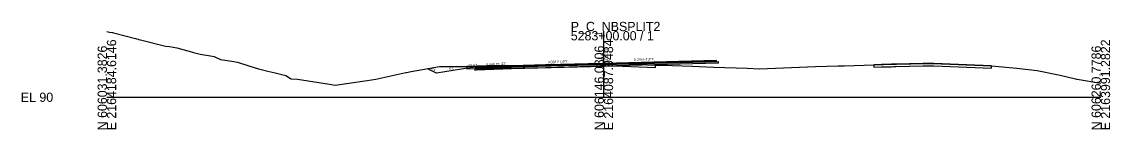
# Model space of a CAD drawing. Extents: x -26 to 1303, y -10 to 12038.
# Drawn here: x -25.7 to 302.8, y 1990.3 to 2022.8 of the extents above; entities that cross this region are included whole.
import ezdxf

# ---------------------------------------------------------------- set-up
doc = ezdxf.new("R2010")
doc.units = 0
for name, color, linetype in [('RD_GPK_XS_Cell', 7, 'Continuous'), ('RD_XS_Base', 7, 'Continuous'), ('RD_XS_ExGround', 7, 'Continuous'), ('RD_XS_ExPaveRet', 7, 'Continuous'), ('RD_XS_Greenside', 7, 'Continuous'), ('RD_XS_Pave', 7, 'Continuous'), ('RD_XS_PaveOvlay_CP', 7, 'Continuous'), ('RD_XS_TieSlope', 7, 'Continuous'), ('RD_XS_TX_Elev_EX', 7, 'Continuous'), ('RD_XS_TX_Elev_PR', 7, 'Continuous'), ('RD_XS_TX_ShdSlope', 7, 'Continuous'), ('RD_XS_TX_Slope', 7, 'Continuous')]:
    doc.layers.add(name, color=color, linetype=linetype)

msp = doc.modelspace()

# ---------------------------------------------------------------- linework, layer by layer
at = {"layer": 'RD_GPK_XS_Cell'}
for p, q in [((150, 2000), (150, 2020)), ((0, 2000), (150, 2000)), ((150, 2000), (300, 2000))]:
    msp.add_line(p, q, dxfattribs=at)
at = {"layer": 'RD_XS_Base'}
for p, q in [((150, 2009.89), (184.5, 2010.79)), ((184, 2010.78), (184, 2010.78)), ((184.5, 2010.79), (184.5, 2010.29)), ((184.5, 2010.76), (184.5, 2010.76)), ((111.52, 2008.75), (111.02, 2008.73)), ((111.02, 2008.73), (111.02, 2008.73)), ((111.02, 2008.73), (111.02, 2008.23)), ((111.02, 2008.23), (111.52, 2008.25)), ((122.09, 2009.17), (111.52, 2008.75)), ((111.52, 2008.75), (111.52, 2008.75)), ((111.52, 2008.25), (122.09, 2008.67)), ((111.52, 2008.25), (111.52, 2008.25)), ((150, 2009.89), (122.09, 2009.17)), ((122.09, 2008.67), (150, 2009.39)), ((138, 2009.58), (138, 2009.58)), ((138, 2009.08), (138, 2009.08)), ((184.5, 2010.29), (150, 2009.39)), ((150, 2009.39), (150, 2010.05)), ((150, 2010.05), (150, 2010.05)), ((150, 2010.05), (150, 2010.05)), ((150, 2010.05), (150, 2009.89)), ((150, 2009.89), (150, 2009.89)), ((150, 2009.39), (150, 2009.89)), ((150, 2009.89), (150, 2009.89)), ((150, 2009.89), (150, 2009.89)), ((150, 2009.39), (150, 2009.39)), ((174, 2010.52), (174, 2010.52)), ((174, 2010.52), (174, 2010.52)), ((174, 2010.02), (174, 2010.02)), ((174, 2010.02), (174, 2010.02))]:
    msp.add_line(p, q, dxfattribs=at)
at = {"layer": 'RD_XS_ExGround'}
msp.add_lwpolyline([(0, 2019.9), (0.83, 2019.72), (1.73, 2019.56), (1.99, 2019.5), (8.66, 2017.75), (8.98, 2017.66), (9.4, 2017.53), (9.57, 2017.49), (10.13, 2017.34), (17.69, 2015.48), (18.94, 2015.39), (21.1, 2014.91), (24.43, 2014.03), (24.85, 2013.9), (26.13, 2013.5), (28.13, 2012.98), (31.26, 2012.51), (32.39, 2012.28), (34.25, 2011.43), (37.72, 2010.87), (39.47, 2010.57), (42.85, 2009.53), (45.73, 2008.61), (46.21, 2008.5), (46.57, 2008.37), (48.58, 2007.91), (50.42, 2007.47), (53.98, 2006.6), (55.46, 2005.63), (55.55, 2005.57), (55.64, 2005.53), (57.55, 2005.43), (67.14, 2003.94), (68.92, 2003.69), (78.57, 2005.1), (81.17, 2005.5), (88.45, 2007.1), (90.26, 2007.49), (90.4, 2007.52), (91.79, 2007.76), (100.43, 2009.27), (101.15, 2009.27), (108.69, 2009.33), (114.75, 2009.45), (118.36, 2009.5), (118.48, 2009.5), (125.69, 2009.64), (132.36, 2009.77), (132.51, 2009.77), (132.73, 2009.78), (149.48, 2010.23), (149.75, 2010.26), (149.85, 2010.25), (150.35, 2010.27), (151.84, 2010.25), (155.64, 2010.12), (165.62, 2009.75), (170.67, 2009.59), (176.66, 2009.38), (183.16, 2009.12), (193.25, 2008.8), (196.96, 2008.63), (201.77, 2008.77), (213.84, 2009.32), (220.68, 2009.46), (222.67, 2009.52), (225.68, 2009.62), (231.5, 2009.83), (234.44, 2009.91), (237.59, 2009.98), (238.36, 2010.02), (247.11, 2010.23), (247.32, 2010.22), (248.79, 2010.24), (249.41, 2010.22), (266.96, 2009.53), (274.69, 2008.82), (280.81, 2008.07), (286.7, 2006.87), (287.77, 2006.66), (292.35, 2005.57), (292.62, 2005.5), (292.62, 2005.5), (292.87, 2005.46), (300, 2004.27)], dxfattribs=at)
at = {"layer": 'RD_XS_ExPaveRet'}
for points in [[(165.62, 2009.75), (155.64, 2010.12), (155.64, 2010.12), (151.84, 2010.25), (150.35, 2010.27), (150.35, 2010.27), (150.35, 2010.27), (149.85, 2010.25), (149.75, 2010.26), (149.48, 2010.23), (149.48, 2010.23), (149.48, 2010.23), (149.48, 2010.23), (132.73, 2009.78), (132.73, 2009.78), (132.51, 2009.77), (132.36, 2009.77), (132.36, 2009.77), (125.69, 2009.64), (125.69, 2009.64), (118.48, 2009.5), (118.48, 2009.5), (118.36, 2009.5), (114.75, 2009.45), (114.75, 2009.45), (114.75, 2009.45), (108.69, 2009.33), (108.69, 2009.33), (108.69, 2009.33), (108.69, 2009.33), (108.69, 2008.58), (108.69, 2008.58), (108.69, 2008.58), (114.75, 2008.7), (114.75, 2008.7), (114.75, 2008.7), (118.36, 2008.75), (118.48, 2008.75), (118.48, 2008.75), (125.69, 2008.89), (125.69, 2008.89), (132.36, 2009.02), (132.36, 2009.02), (132.51, 2009.02), (132.73, 2009.03), (132.73, 2009.03), (149.48, 2009.48), (149.48, 2009.48), (149.48, 2009.48), (149.48, 2009.48), (149.75, 2009.51), (149.85, 2009.5), (150.35, 2009.52), (150.35, 2009.52), (150.35, 2009.52), (151.84, 2009.5), (155.64, 2009.37), (155.64, 2009.37), (165.62, 2009), (165.62, 2009), (165.62, 2009.75), (165.62, 2009.75), (165.62, 2009.75)], [(165.62, 2009.75), (155.64, 2010.12), (151.84, 2010.25), (150.35, 2010.27), (149.85, 2010.25), (149.75, 2010.26), (149.48, 2010.23), (132.73, 2009.78), (132.51, 2009.77), (132.36, 2009.77), (125.69, 2009.64), (118.48, 2009.5), (118.36, 2009.5), (114.75, 2009.45), (108.69, 2009.33), (108.69, 2008.58), (114.75, 2008.7), (118.36, 2008.75), (118.48, 2008.75), (125.69, 2008.89), (132.36, 2009.02), (132.51, 2009.02), (132.73, 2009.03), (149.48, 2009.48), (149.75, 2009.51), (149.85, 2009.5), (150.35, 2009.52), (151.84, 2009.5), (155.64, 2009.37), (165.62, 2009), (165.62, 2009.75)], [(266.96, 2009.53), (264.47, 2009.63), (249.6, 2010.22), (248.9, 2010.24), (248.81, 2010.24), (248.73, 2010.24), (247.44, 2010.22), (247.32, 2010.22), (247.17, 2010.23), (247.11, 2010.23), (246.61, 2010.22), (246.42, 2010.21), (238.17, 2010.01), (237.43, 2010), (236.85, 2009.96), (234.44, 2009.91), (233.77, 2009.9), (231.5, 2009.83), (231.5, 2009.74), (231.5, 2009.08), (233.77, 2009.15), (234.44, 2009.16), (236.85, 2009.21), (237.43, 2009.25), (238.17, 2009.26), (246.42, 2009.46), (246.61, 2009.47), (247.11, 2009.48), (247.17, 2009.48), (247.32, 2009.47), (247.44, 2009.47), (248.73, 2009.49), (248.81, 2009.49), (248.9, 2009.49), (249.6, 2009.47), (264.47, 2008.88), (266.96, 2008.78), (266.96, 2008.78), (266.96, 2008.78), (266.96, 2009.39), (266.96, 2009.53), (266.96, 2009.53), (266.96, 2009.53)], [(266.96, 2009.53), (264.47, 2009.63), (249.6, 2010.22), (248.9, 2010.24), (248.81, 2010.24), (248.73, 2010.24), (247.44, 2010.22), (247.32, 2010.22), (247.17, 2010.23), (247.11, 2010.23), (246.61, 2010.22), (246.42, 2010.21), (238.17, 2010.01), (237.43, 2010), (236.85, 2009.96), (234.44, 2009.91), (233.77, 2009.9), (231.5, 2009.83), (231.5, 2009.74), (231.5, 2009.08), (233.77, 2009.15), (234.44, 2009.16), (236.85, 2009.21), (237.43, 2009.25), (238.17, 2009.26), (246.42, 2009.46), (246.61, 2009.47), (247.11, 2009.48), (247.17, 2009.48), (247.32, 2009.47), (247.44, 2009.47), (248.73, 2009.49), (248.81, 2009.49), (248.9, 2009.49), (249.6, 2009.47), (264.47, 2008.88), (266.96, 2008.78), (266.96, 2008.78), (266.96, 2009.39), (266.96, 2009.53), (266.96, 2009.53)]]:
    msp.add_lwpolyline(points, dxfattribs=at)
at = {"layer": 'RD_XS_Greenside'}
for p, q in [((99.52, 2007.24), (96.74, 2008.62)), ((109.52, 2008.9), (99.52, 2007.24))]:
    msp.add_line(p, q, dxfattribs=at)
at = {"layer": 'RD_XS_Pave'}
for p, q in [((184, 2011.1), (150, 2010.21)), ((184, 2010.94), (150, 2010.05)), ((150, 2010.05), (184, 2010.94)), ((150, 2009.89), (184, 2010.78)), ((174, 2010.84), (174, 2010.84)), ((174, 2010.84), (174, 2010.84)), ((174, 2010.68), (174, 2010.68)), ((174, 2010.68), (174, 2010.68)), ((174, 2010.68), (174, 2010.68)), ((174, 2010.68), (174, 2010.68)), ((184, 2010.94), (184, 2011.1)), ((184, 2011.1), (184, 2011.1)), ((184, 2010.78), (184, 2010.94)), ((184, 2010.94), (184, 2010.94)), ((122.09, 2009.49), (111.52, 2009.06)), ((111.52, 2008.91), (122.09, 2009.33)), ((122.09, 2009.33), (111.52, 2008.91)), ((111.52, 2008.75), (122.09, 2009.17)), ((111.52, 2009.06), (111.52, 2009.06)), ((111.52, 2009.06), (111.52, 2008.91)), ((111.52, 2008.91), (111.52, 2008.91)), ((111.52, 2008.91), (111.52, 2008.75)), ((150, 2010.21), (122.09, 2009.49)), ((122.09, 2009.33), (150, 2010.05)), ((150, 2010.05), (122.09, 2009.33)), ((122.09, 2009.17), (150, 2009.89)), ((138, 2009.9), (138, 2009.9)), ((138, 2009.74), (138, 2009.74)), ((138, 2009.74), (138, 2009.74)), ((138, 2009.58), (138, 2009.58)), ((150, 2010.21), (150, 2010.21)), ((150, 2010.05), (150, 2010.05)), ((150, 2010.05), (150, 2010.05)), ((150, 2010.05), (150, 2009.89)), ((150, 2010.05), (150, 2010.05)), ((150, 2009.89), (150, 2010.05)), ((150, 2010.05), (150, 2010.05)), ((150, 2010.05), (150, 2010.05)), ((150, 2009.89), (150, 2009.89)), ((150, 2009.89), (150, 2009.89)), ((174, 2010.52), (174, 2010.52)), ((174, 2010.52), (174, 2010.52))]:
    msp.add_line(p, q, dxfattribs=at)
at = {"layer": 'RD_XS_PaveOvlay_CP'}
for p, q in [((184, 2011.1), (150, 2010.21)), ((174, 2010.84), (174, 2010.84)), ((174, 2010.84), (174, 2010.84)), ((122.09, 2009.49), (111.52, 2009.06)), ((150, 2010.21), (122.09, 2009.49)), ((138, 2009.9), (138, 2009.9)), ((150, 2010.21), (150, 2010.21))]:
    msp.add_line(p, q, dxfattribs=at)
at = {"layer": 'RD_XS_TieSlope'}
msp.add_line((111.52, 2009.06), (109.52, 2008.9), dxfattribs=at)

# ---------------------------------------------------------------- texts
at = {"layer": 'RD_GPK_XS_Cell'}
for s, p in [('P_C_NBSPLIT2', (140, 2020)), ('5283+00.00 / 1', (140, 2017.2)), ('EL 90', (-26, 1998.6))]:
    msp.add_text(s, height=2.8, dxfattribs=at).set_placement(p)
for s, p in [('E 2164184.6146', (2.8, 1990)), ('E 2164087.9484', (152.8, 1990)), ('E 2163991.2822', (302.8, 1990)), ('N 606031.3826', (0, 1990)), ('N 606146.0806', (150, 1990)), ('N 606260.7786', (300, 1990))]:
    msp.add_text(s, height=2.8, rotation=90, dxfattribs=at).set_placement(p)
at = {"layer": 'RD_XS_TX_Elev_EX'}
msp.add_text('100.26', height=0.6, rotation=90, dxfattribs=at).set_placement((149.74, 2010.86))
at = {"layer": 'RD_XS_TX_Elev_PR'}
msp.add_text('100.21', height=1, rotation=90, dxfattribs=at).set_placement((151.24, 2010.5))
at = {"layer": 'RD_XS_TX_ShdSlope'}
msp.add_text('12.5:1', height=0.75, rotation=4.5739, dxfattribs=at).set_placement((109.09, 2009.15))
at = {"layer": 'RD_XS_TX_Slope'}
for s, rotation, p in [('0.028 FT./FT.', 1.6039, (133.06, 2010.25)), ('0.028 FT./FT.', 1.6039, (159.06, 2010.97)), ('2:1', 333.4349, (97.74, 2008.52)), ('6:1', 9.4642, (103.32, 2008.28)), ('0.040 FT./FT.', 2.2906, (114.48, 2009.48))]:
    msp.add_text(s, height=0.75, rotation=rotation, dxfattribs=at).set_placement(p)

doc.saveas('drawing.dxf')
